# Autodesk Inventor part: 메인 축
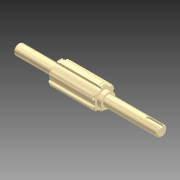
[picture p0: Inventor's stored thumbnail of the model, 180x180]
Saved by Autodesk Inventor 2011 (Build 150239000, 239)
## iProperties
Created: 2012-05
Part Number: 메인 축
Document SubType Name: 모델링
Designer: SeoGD™
Mass: 168.567 g
Surface Area: 72.5109 cm^2
Volume: 21.4462 cm^3
Density: 7.86 g/cm^3
Material: 강, 연강
변환 표준: STEP AP214IS
파일 이름: C:\Users\SeoGD\Desktop\?쒗뿕\硫붿씤 異?.stp
전처리기: Build: 253, Release: 2010 SP1 - Date: Wed 07/29/2009
전송 단위: 밀리미터
불확실성: 0.01
Author: SeoGD™
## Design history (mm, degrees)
sketch "스케치1"
  geometry: L1 (-69.5, 0)-(69.5, 0); L2 (69.5, 0)-(69.5, 5); L3 (69.5, 5)-(55.5, 5); L4 (55.5, 5)-(55.5, 4.8); L5 (55.5, 4.8)-(54.35, 4.8); L6 (54.35, 4.8)-(54.35, 5); L7 (54.35, 5)-(30.5, 5); L8 (30.5, 5)-(30.5, 9); L9 (30.5, 9)-(-13.5, 9); L10 (-13.5, 9)-(-13.5, 7); L11 (-13.5, 7)-(-17.5, 7); L12 (-17.5, 7)-(-17.5, 5); L13 (-17.5, 5)-(-69.5, 5); L14 (-69.5, 5)-(-69.5, 0); 2 further points
  constraints: 28 end point, 9 parallel, 4 collinear, 2 perpendicular, 1 coincident, 1 horizontal, 1 midpoint
  dimensions: "d2" = 1.15 distance between parallel lines of L6 L4; "d3" = 10 diameter of L3 L1; "d4" = 9.6 diameter of L5 L1; "d6" = 44 distance between parallel lines of L10 L8; "d7" = 4 distance between parallel lines of L12 L10; "d8" = 14 diameter of L11 L1; "d9" = 18 diameter of L9 L1; "d33" = 52 distance from line of L12.end L14; "d37" = 39 distance between parallel lines of L8 L2; "d38" = 14 distance between parallel lines of L2 L4
revolve "회전1" sketch "스케치1" stored, may be unused: angle "d10" = 90 deg
sketch "스케치2"
  geometry: L1 (2.5, 10.712)-(2.5, 8.646); L2 (-2.5, 10.712)-(-2.5, 8.646); A1 r 9 centre (0, 0) between (2.5, 8.646) and (-2.5, 8.646) reference; A2 r 11 centre (0, 0) between (2.5, 10.712) and (-2.5, 10.712); 1 further point
  constraints: 4 end point, 4 point on circle, 2 parallel, 1 centre point, 1 coincident, 1 vertical
  dimensions: "d11" = 22 diameter of A2; "d12" = 5 distance between parallel lines of L1 L2
extrude "돌출1" join sketch "스케치2" stored distance "d13" = 10; taper "d14" = 0 deg
chamfer "모따기1" distance "d15" = 1; stored, may be unused: second distance "d16" = 2, angle "d17" = 45 deg
node "작업 평면1"
node "작업 평면2"
sketch "스케치3"
  geometry: L1 (2.5, 10.712)-(2.5, 10.198); L2 (-2.5, 10.712)-(-2.5, 10.198); A1 r 11 centre (0, 0) between (2.5, 10.712) and (-2.5, 10.712) reference; A2 r 10.5 centre (0, 0) between (2.5, 10.198) and (-2.5, 10.198); 1 further point
  constraints: 4 end point, 2 point on circle, 1 centre point, 1 coincident, 1 parallel, 1 vertical
  dimensions: "d19" = 21 diameter of A2
extrude "돌출2" cut sketch "스케치3" distance "d20" = 1.35; taper "d21" = 0 deg
node "작업 평면3"
sketch "스케치4"
  geometry: L1 (-26, -5)-(-26, 5) reference; L2 (-26, 1.5)-(-12.5, 1.5); L3 (-12.5, -1.5)-(-26, -1.5); A1 r 1.5 centre (-12.5, 0) between (-12.5, -1.5) and (-12.5, 1.5); 2 further points
  constraints: 4 end point, 2 perpendicular, 2 point on circle, 2 point on line, 2 tangent, 1 centre point, 1 horizontal alignment, 1 midpoint
  dimensions: "d25" = 3 distance between parallel lines of L3 L2; "d26" = 15 dimension on A1 L1
extrude "돌출3" cut sketch "스케치4" distance "d27" = 1.8; taper "d28" = 0 deg
chamfer "모따기2" distance "d29" = 1; stored, may be unused: second distance "d30" = 2, angle "d31" = 45 deg
node "솔리드1"
node "솔리드 본체"
node "곡면 본체"
mirror "대칭1"
pattern_circular "원형 패턴1" dims "d23" = 360 deg
node "솔리드2"
other parameters: "d18" = -1.65
